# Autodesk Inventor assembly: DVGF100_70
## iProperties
Created: 2010-04
Part Number: DVGF100_70
Document SubType Name: Assembly
Designer: TB
Mass: 3402.64 g
Surface Area: 3442.35 cm^2
Volume: 3402.64 cm^3
Density: 1 g/cm^3
Description: KM DVGF 100/70 - 100 mm
Slaglengde: 100.000 mm
Author: TB
